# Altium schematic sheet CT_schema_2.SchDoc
size 383 x 311 mm
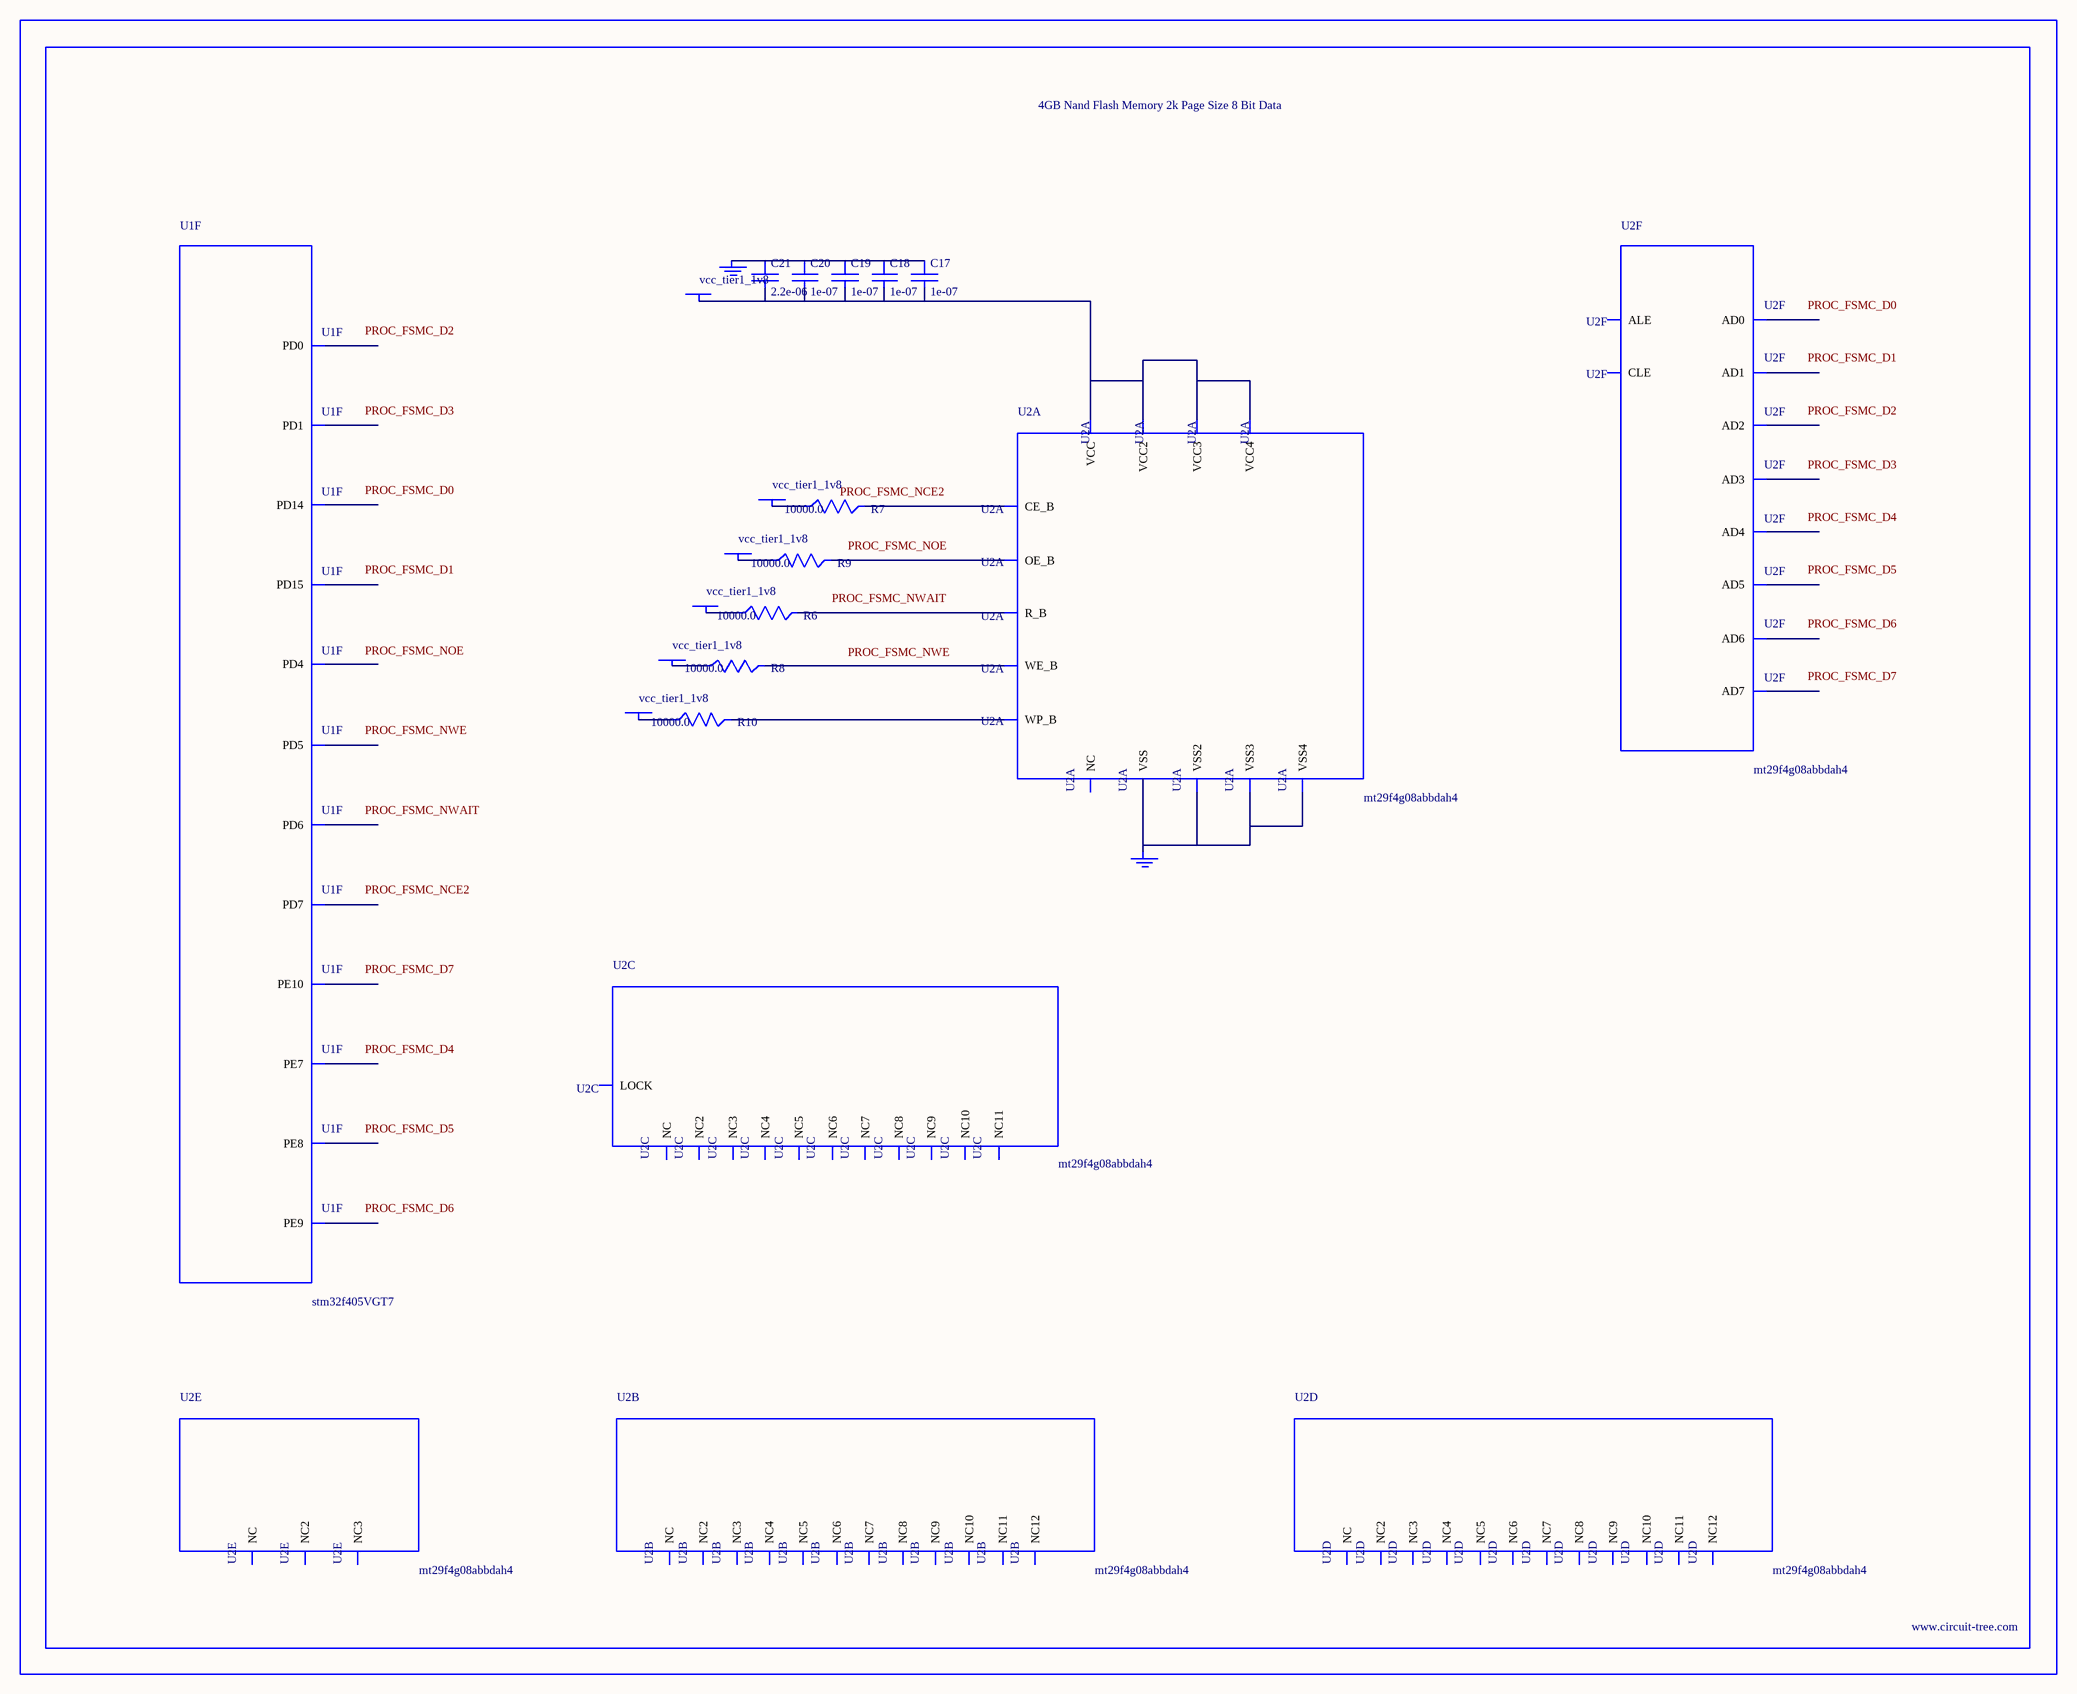
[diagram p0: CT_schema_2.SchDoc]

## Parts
BORDER1  (no value)
C17  1e-07  [C0402]
C18  1e-07  [C0402]
C19  1e-07  [C0402]
C20  1e-07  [C0402]
C21  2.2e-06  [C0603]
GND_INSTANCE_1_0  (no value)
GND_INSTANCE_1_1  (no value)
POWER_INSTANCE_1_0  vcc_tier1_1v8
POWER_INSTANCE_1_1  vcc_tier1_1v8
POWER_INSTANCE_1_2  vcc_tier1_1v8
POWER_INSTANCE_1_3  vcc_tier1_1v8
POWER_INSTANCE_1_4  vcc_tier1_1v8
POWER_INSTANCE_1_5  vcc_tier1_1v8
R6  10000.0  [R0603]
R7  10000.0  [R0603]
R8  10000.0  [R0603]
R9  10000.0  [R0603]
R10  10000.0  [R0603]
U1  stm32f405VGT7  [LQFP100]  (part F of 10)
U2  mt29f4g08abbdah4  [VFBGA-63]  (parts A,B,C,D,E,F of 6)

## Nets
NetC17_1: C17.1 C18.1 C19.1 C20.1 C21.1 GND_INSTANCE_1_0.0(GND)
NetC17_2: C17.2 C18.2 C19.2 C20.2 C21.2 POWER_INSTANCE_1_0.0(PWR) U2.D3(VCC) U2.G4(VCC2) U2.H8(VCC3) U2.J6(VCC4)
NetGND_INSTANCE_1_1_0: GND_INSTANCE_1_1.0(GND) U2.C5(VSS) U2.F7(VSS2) U2.K3(VSS3) U2.K8(VSS4)
NetPOWER_INSTANCE_1_1_0: POWER_INSTANCE_1_1.0(PWR) R6.1
NetPOWER_INSTANCE_1_2_0: POWER_INSTANCE_1_2.0(PWR) R7.1
NetPOWER_INSTANCE_1_3_0: POWER_INSTANCE_1_3.0(PWR) R8.1
NetPOWER_INSTANCE_1_4_0: POWER_INSTANCE_1_4.0(PWR) R9.1
NetPOWER_INSTANCE_1_5_0: POWER_INSTANCE_1_5.0(PWR) R10.1
NetR6_2: R6.2 U2.C8(R_B)
NetR7_2: R7.2 U2.C6(CE_B)
NetR8_2: R8.2 U2.C7(WE_B)
NetR9_2: R9.2 U2.D4(OE_B)
NetR10_2: R10.2 U2.C3(WP_B)

Not connected (* = marked no-connect by the designer): U1 38(PE7) 39(PE8) 40(PE9) 41(PE10) 61(PD14) 62(PD15) 81(PD0) 82(PD1) 85(PD4) 86(PD5) 87(PD6) 88(PD7); U2 A1(NC) A2(NC3) A9(NC4) A10(NC2) B1(NC5) B9(NC7) B10(NC6) C4(ALE) D5(CLE) D6(NC8) D7(NC9) D8(NC10) E3(NC11) E4(NC12) E5(NC) E6(NC2) E7(NC3) E8(NC4) F3(NC5) F4(NC6) F5(NC7) F6(NC8) F8(NC9) G3(NC) G5(LOCK) G6(NC10) G7(NC11) G8(NC) H3(NC2) H4(AD0) H5(NC3) H6(NC4) H7(NC5) J3(NC6) J4(AD1) J5(NC7) J7(AD5) J8(AD7) K4(AD2) K5(AD3) K6(AD4) K7(AD6) L1(NC8) L2(NC10) L9(NC11) L10(NC9) M1(NC12) M2(NC2) M9(NC3) M10(NC)

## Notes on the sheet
- Labels drawn without touching a wire or pin: PROC_FSMC_D0, PROC_FSMC_D1, PROC_FSMC_D2, PROC_FSMC_D3, PROC_FSMC_D4, PROC_FSMC_D5, PROC_FSMC_D6, PROC_FSMC_D7, PROC_FSMC_NCE2, PROC_FSMC_NOE, PROC_FSMC_NWAIT, PROC_FSMC_NWE

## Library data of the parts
BORDER1 = BORDER_PAGE1
C17-C20 = C0402C104K3RACTU
C21 = C0603C225K8RACTU
GND_INSTANCE_1_0 GND_INSTANCE_1_1 = GND
POWER_INSTANCE_1_0-POWER_INSTANCE_1_5 = PWR
R6-R10 = RC0603JR-0710KL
